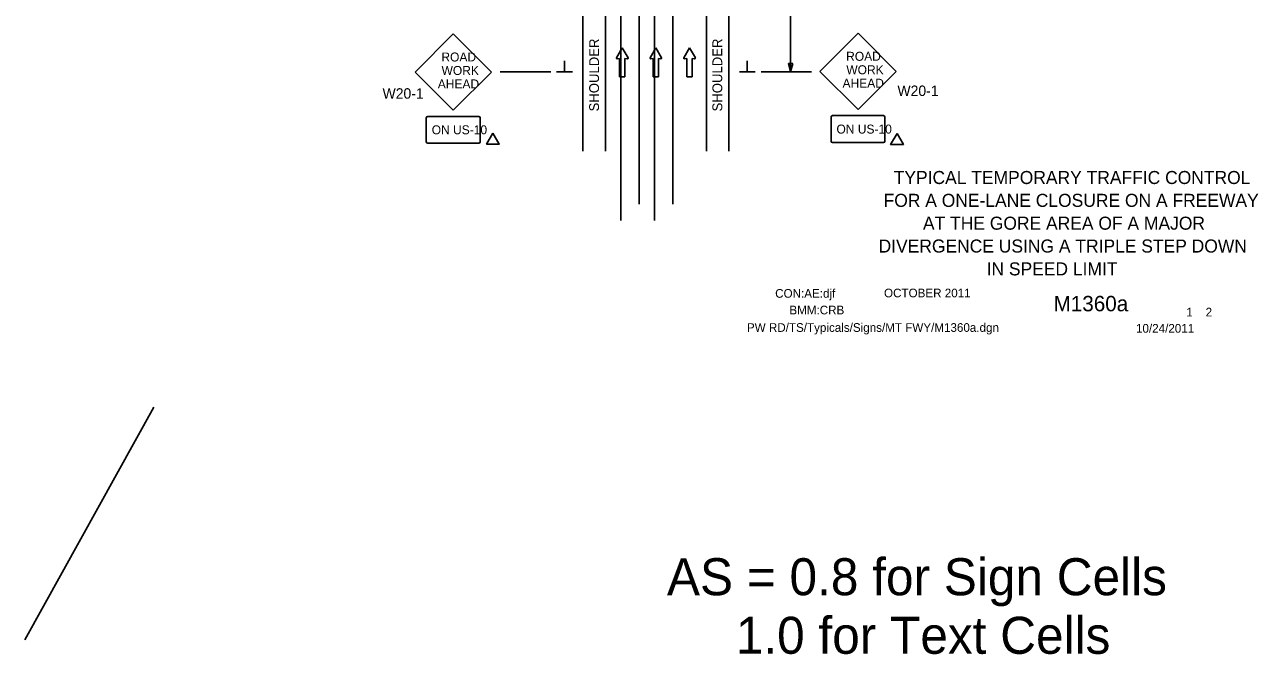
# Model space of a CAD drawing. Extents: x 16556 to 18479, y 5704 to 6974.
# Drawn here: x 16556 to 17435, y 5704 to 6153 of the extents above; entities that cross this region are included whole.
import ezdxf

# ---------------------------------------------------------------- set-up
doc = ezdxf.new("R2010")
doc.units = 0
for name, color, linetype in [('ALI_LEGAL_EX', 7, 'Continuous'), ('BORDER', 7, 'Continuous'), ('BORDER_SIGNAL_WO', 7, 'Continuous'), ('MT_SCRATCH_LEVEL_E', 7, 'Continuous'), ('PAVT_EDGE_EX', 7, 'Continuous'), ('TRAFFIC_SIGNS_PR', 7, 'Continuous'), ('TYPICAL_TEXT_DIMEN_PR', 7, 'Continuous')]:
    doc.layers.add(name, color=color, linetype=linetype)

msp = doc.modelspace()

# ---------------------------------------------------------------- linework, layer by layer
at = {"layer": 'ALI_LEGAL_EX'}
for p, q in [((16980.68, 6877.04), (16980.68, 6013.12)), ((17004.68, 6877.04), (17004.68, 6013.12)), ((16993.65, 6024.8), (16993.65, 6525.15)), ((17017.65, 6024.8), (17017.65, 6525.15))]:
    msp.add_line(p, q, dxfattribs=at)
for points in [[(16993.65, 6124.8), (16993.65, 6149.8)], [(17017.65, 6124.8), (17017.65, 6149.8)], [(16993.65, 6049.8), (16993.65, 6024.8)]]:
    msp.add_lwpolyline(points, dxfattribs=at)
at = {"layer": 'MT_SCRATCH_LEVEL_E'}
for p, q in [((16981.67, 6136.42), (16977.55, 6129.18)), ((16985.81, 6129.18), (16981.67, 6136.42)), ((17005.57, 6136.42), (17001.46, 6129.18)), ((17009.72, 6129.18), (17005.57, 6136.42)), ((17029.62, 6136.42), (17025.51, 6129.18)), ((17033.77, 6129.18), (17029.62, 6136.42)), ((16978.04, 6128.5), (16979.81, 6128.81)), ((16979.81, 6128.81), (16979.81, 6115.56)), ((16983.56, 6115.56), (16983.56, 6128.81)), ((16983.56, 6128.81), (16985.33, 6128.5)), ((17001.94, 6128.5), (17003.72, 6128.81)), ((17003.72, 6128.81), (17003.72, 6115.56)), ((17007.46, 6115.56), (17007.46, 6128.81)), ((17007.46, 6128.81), (17009.24, 6128.5)), ((17025.99, 6128.5), (17027.77, 6128.81)), ((17027.77, 6128.81), (17027.77, 6115.56)), ((17031.51, 6115.56), (17031.51, 6128.81)), ((17031.51, 6128.81), (17033.29, 6128.5)), ((16979.81, 6115.56), (16983.56, 6115.56)), ((17003.72, 6115.56), (17007.46, 6115.56)), ((17027.77, 6115.56), (17031.51, 6115.56))]:
    msp.add_line(p, q, dxfattribs=at)
for centre, start, end in [((16977.96, 6128.96), 150.42484, 279.96381), ((16985.4, 6128.96), 260.03619, 29.77312), ((17001.87, 6128.96), 150.42484, 279.96381), ((17009.31, 6128.96), 260.03619, 29.77312), ((17025.92, 6128.96), 150.42484, 279.96381), ((17033.36, 6128.96), 260.03619, 29.77312)]:
    msp.add_arc(centre, 0.463, start, end, dxfattribs=at)
at = {"layer": 'PAVT_EDGE_EX'}
for p, q in [((16953.65, 6525.15), (16953.65, 6062.71)), ((16969.65, 6525.15), (16969.65, 6062.71)), ((17041.65, 6525.15), (17041.65, 6062.71)), ((17057.65, 6525.15), (17057.65, 6062.71))]:
    msp.add_line(p, q, dxfattribs=at)
at = {"layer": 'TRAFFIC_SIGNS_PR'}
for p, q in [((16861.19, 6146.23), (16834.04, 6119.07)), ((16888.35, 6119.07), (16861.19, 6146.23)), ((17149.75, 6146.73), (17122.59, 6119.58)), ((17176.9, 6119.58), (17149.75, 6146.73)), ((16834.04, 6119.07), (16861.19, 6091.91)), ((16861.19, 6091.91), (16888.35, 6119.07)), ((17122.59, 6119.58), (17149.75, 6092.42)), ((17149.75, 6092.42), (17176.9, 6119.58)), ((16841.99, 6086.47), (16841.99, 6069.27)), ((16842.99, 6087.47), (16879.4, 6087.47)), ((16880.4, 6086.47), (16880.4, 6069.27)), ((17130.55, 6086.98), (17130.55, 6069.77)), ((17131.55, 6087.98), (17167.95, 6087.98)), ((17168.95, 6086.98), (17168.95, 6069.77)), ((17131.55, 6068.77), (17167.95, 6068.77)), ((16842.99, 6068.27), (16879.4, 6068.27))]:
    msp.add_line(p, q, dxfattribs=at)
for centre, start, end in [((16842.99, 6086.47), 90, 180), ((16879.4, 6086.47), 0, 90), ((17131.55, 6086.98), 90, 180), ((17167.95, 6086.98), 0, 90), ((16842.99, 6069.27), 180, 270), ((16879.4, 6069.27), 270, 0), ((17131.55, 6069.77), 180, 270), ((17167.95, 6069.77), 270, 0)]:
    msp.add_arc(centre, 1, start, end, dxfattribs=at)
at = {"layer": 'TYPICAL_TEXT_DIMEN_PR'}
for p, q in [((17101.65, 6219.33), (17101.65, 6119.33)), ((16940.52, 6119.33), (16940.52, 6127.11)), ((17070.77, 6119.33), (17070.77, 6127.11)), ((17101.65, 6119.33), (17100.08, 6125.19)), ((17100.08, 6125.19), (17101.65, 6125.19)), ((17101.65, 6125.19), (17103.22, 6125.19)), ((17103.22, 6125.19), (17101.65, 6119.33)), ((16930.65, 6119.33), (16894.65, 6119.33)), ((16934.9, 6119.33), (16946.15, 6119.33)), ((17076.4, 6119.33), (17065.15, 6119.33)), ((17080.65, 6119.33), (17116.65, 6119.33)), ((16647.75, 5880), (16555.64, 5713.9))]:
    msp.add_line(p, q, dxfattribs=at)
for points in [[(16889.45, 6075.47), (16884.92, 6067.64), (16893.97, 6067.64)], [(17177.55, 6075.28), (17173.02, 6067.44), (17182.07, 6067.44)]]:
    msp.add_lwpolyline(points, close=True, dxfattribs=at)

# ---------------------------------------------------------------- texts
at = {"layer": 'BORDER'}
for s, p in [('TYPICAL TEMPORARY TRAFFIC CONTROL', (17175.21, 6039.19)), ('FOR A ONE-LANE CLOSURE ON A FREEWAY', (17167.99, 6022.89)), ('AT THE GORE AREA OF A MAJOR', (17196.04, 6006.6)), ('DIVERGENCE USING A TRIPLE STEP DOWN ', (17164.42, 5990.3)), ('IN SPEED LIMIT', (17241.42, 5974))]:
    msp.add_text(s, height=9.3, dxfattribs=at).set_placement(p)
at = {"layer": 'BORDER_SIGNAL_WO'}
for s, height, p in [('CON:AE:djf  ', 6.2, (17090.69, 5958.06)), ('    OCTOBER 2011    ', 6.2, (17159.08, 5958.34)), ('    M1360a   ', 11, (17272.86, 5948.38)), ('BMM:CRB   ', 6.2, (17100.81, 5946.17)), (' 1    2 ', 6.2, (17381.45, 5944.7)), ('PW RD/TS/Typicals/Signs/MT FWY/M1360a.dgn      ', 6.2, (17070.55, 5933.71)), ('10/24/2011    ', 6.2, (17347.93, 5933.13)), ('AS = 0.8 for Sign Cells', 26.4241, (17013.51, 5745.8)), ('     1.0 for Text Cells', 26.4241, (17013.51, 5704.01))]:
    msp.add_text(s, height=height, dxfattribs=at).set_placement(p)
at = {"layer": 'TRAFFIC_SIGNS_PR'}
for s, height, p in [('ROAD', 6.401, (16852.73, 6126.61)), ('ROAD', 6.401, (17141.29, 6127.11)), ('WORK', 6.401, (16852.84, 6117.01)), ('WORK', 6.401, (17141.4, 6117.51)), ('AHEAD', 6.401, (16850.15, 6107.4)), ('AHEAD', 6.401, (17138.71, 6107.91)), ('W20-1', 7.441, (16810.78, 6100.08)), ('W20-1', 7.441, (17177.85, 6102.01)), ('ON US-10', 6.401, (16845.83, 6074.67)), ('ON US-10', 6.401, (17134.38, 6075.18))]:
    msp.add_text(s, height=height, dxfattribs=at).set_placement(p)
at = {"layer": 'TYPICAL_TEXT_DIMEN_PR'}
for p in [(16965.09, 6090.97), (17052.95, 6090.97)]:
    msp.add_text('SHOULDER', height=7, rotation=90, dxfattribs=at).set_placement(p)

doc.saveas('drawing.dxf')
